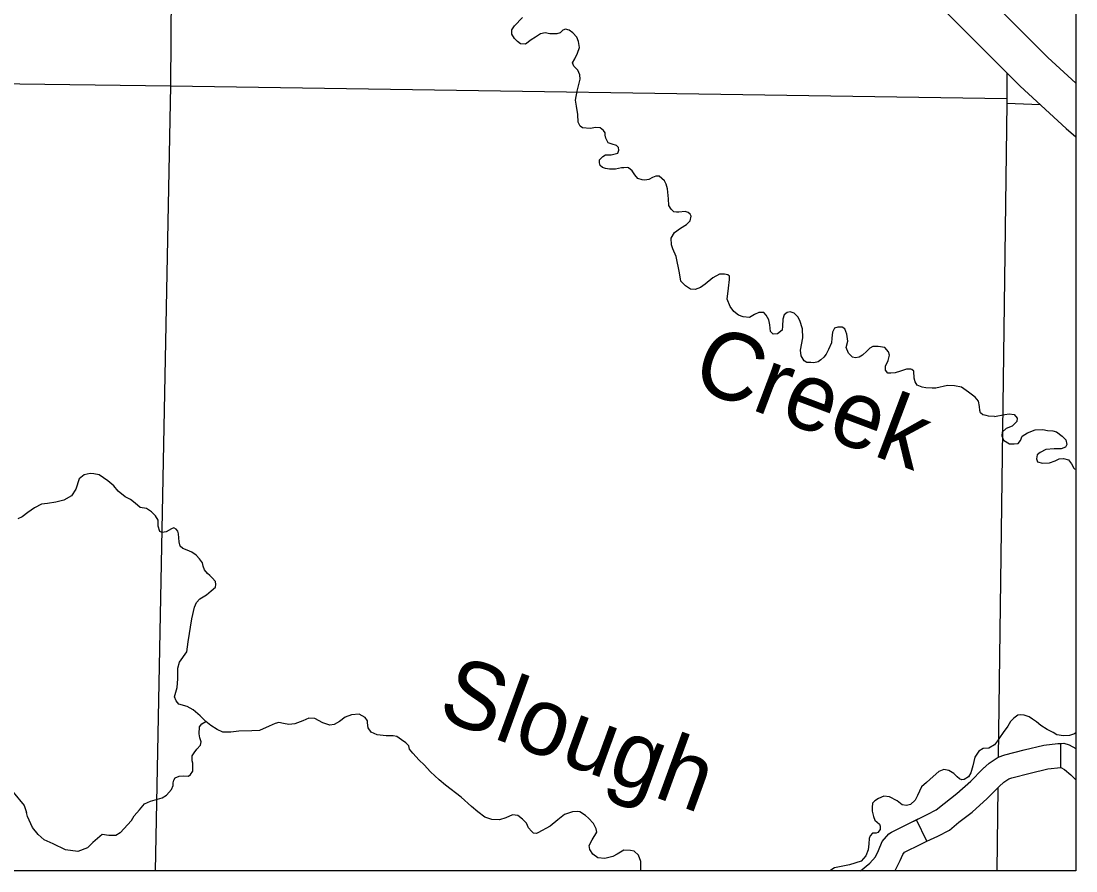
# Model space of a CAD drawing. Extents: x 8749 to 11879, y 13275 to 15339.
# Drawn here: x 10827.5 to 10959.7, y 13439.9 to 13546.4 of the extents above; entities that cross this region are included whole.
import ezdxf

# ---------------------------------------------------------------- set-up
doc = ezdxf.new("R2010")
doc.units = 0
for name, color, linetype in [('Level 10', 7, 'Continuous'), ('Level 35', 7, 'Continuous'), ('Level 4', 7, 'Continuous'), ('Level 45', 7, 'Continuous'), ('Level 5', 7, 'Continuous'), ('R_Draft', 7, 'Continuous')]:
    doc.layers.add(name, color=color, linetype=linetype)

msp = doc.modelspace()

# ---------------------------------------------------------------- linework, layer by layer
at = {"layer": 'Level 10'}
for points in [[(10959.72, 13538.61), (10956.22, 13541.83), (10954.17, 13543.9), (10948.32, 13549.78), (10940.49, 13557.65), (10939.11, 13559.13), (10938.56, 13559.8), (10938.03, 13560.67), (10937.75, 13561.23), (10937.61, 13561.73), (10937.29, 13563.06), (10937.16, 13563.75), (10937.14, 13565.49), (10937.14, 13568.12), (10937.11, 13569.39), (10936.92, 13570.54), (10936.72, 13571.84), (10936.36, 13573.13), (10935.94, 13574.18), (10935.26, 13575.82), (10934.06, 13578.06)], [(10929.65, 13575.7), (10930.73, 13573.68), (10931.3, 13572.3), (10931.61, 13571.52), (10931.83, 13570.77), (10931.99, 13569.76), (10932.12, 13568.93), (10932.14, 13568.06), (10932.14, 13565.46), (10932.17, 13563.25), (10932.4, 13562.01), (10932.76, 13560.51), (10933.05, 13559.45), (10933.65, 13558.23), (10934.48, 13556.89), (10935.34, 13555.84), (10936.89, 13554.18), (10944.77, 13546.25), (10950.62, 13540.37), (10952.75, 13538.23), (10958.49, 13532.93), (10959.72, 13531.89)]]:
    msp.add_lwpolyline(points, dxfattribs=at)
at = {"layer": 'Level 35'}
for points in [[(10889.33, 13545.83), (10890.36, 13546.87)], [(10898.82, 13532.94), (10897.89, 13533.01), (10897.59, 13533.24), (10897.31, 13533.75), (10897.28, 13534.68), (10897.13, 13535.74), (10897.01, 13536.48), (10897.21, 13537.64), (10897.59, 13539.11), (10897.54, 13539.69), (10897.28, 13540.25), (10896.8, 13540.75), (10896.63, 13541.16), (10896.93, 13541.66), (10897.23, 13542.39), (10897.49, 13543.08), (10897.36, 13543.84), (10897.18, 13544.39), (10896.65, 13544.92), (10896.2, 13545.28), (10895.74, 13545.38), (10895.41, 13545.25), (10895.06, 13544.92), (10894.66, 13544.8), (10893.77, 13544.82), (10893.17, 13544.92), (10892.61, 13544.8), (10891.98, 13544.39), (10891.42, 13544.04), (10890.72, 13543.53), (10890.11, 13543.56), (10889.71, 13543.84), (10889.33, 13544.21), (10889, 13544.75), (10889, 13545.3), (10889.33, 13545.83)], [(10904.08, 13527.62), (10903.65, 13528.01), (10903.49, 13528.04), (10903.04, 13528.01), (10902.74, 13527.99), (10902, 13527.86), (10901.27, 13527.86), (10900.77, 13527.91), (10900.39, 13528.04), (10900.08, 13528.32), (10900.01, 13528.62), (10900.01, 13529.02), (10900.41, 13529.45), (10900.77, 13529.63), (10901.47, 13529.63), (10902.28, 13529.86), (10902.43, 13530.24), (10902.38, 13530.57), (10902.13, 13530.82), (10901.6, 13530.97), (10901.09, 13531.15), (10900.79, 13531.73), (10900.72, 13532.11), (10900.72, 13532.41), (10900.49, 13532.69), (10900.08, 13533.02), (10899.53, 13533.07), (10898.82, 13532.94)], [(10910.79, 13513.23), (10910.21, 13513.82), (10910.01, 13514.83), (10909.61, 13516.9), (10909.18, 13517.84), (10909.03, 13518.37), (10909, 13519.18), (10909.4, 13519.91), (10910.16, 13520.44), (10910.89, 13520.9), (10911.35, 13521.38), (10911.48, 13521.96), (10911.37, 13522.21), (10911.12, 13522.42), (10910.74, 13522.52), (10909.96, 13522.44), (10909.66, 13522.44), (10909.3, 13522.49), (10909, 13522.82), (10908.7, 13523.28), (10908.65, 13524.11), (10908.52, 13525.37), (10908.37, 13525.98), (10908.17, 13526.39), (10907.46, 13526.97), (10907.06, 13526.97), (10906.63, 13526.79), (10906.17, 13526.56), (10905.69, 13526.46), (10905.36, 13526.49), (10904.81, 13526.69), (10904.43, 13527.14), (10904.08, 13527.62)], [(10926.87, 13503.57), (10926.5, 13503.62), (10925.99, 13503.62), (10925.64, 13503.8), (10925.29, 13504.46), (10925.19, 13505.14), (10925.49, 13506.71), (10925.44, 13507.82), (10925.11, 13508.88), (10924.88, 13509.31), (10924.4, 13509.77), (10923.9, 13509.94), (10923.52, 13509.89), (10923.17, 13509.59), (10922.99, 13509.03), (10922.96, 13508.17), (10922.89, 13507.64), (10922.33, 13507.21), (10921.75, 13507.16), (10921.42, 13507.49), (10921.35, 13508.33), (10921.22, 13508.96), (10920.89, 13509.56), (10920.59, 13509.87), (10919.98, 13509.89), (10919.45, 13509.62), (10918.8, 13509.24), (10917.99, 13509.31), (10917.43, 13509.56), (10916.85, 13509.99), (10916.37, 13510.63), (10916.02, 13511.54), (10916.19, 13512.93), (10916.3, 13513.99), (10916.3, 13514.42), (10916.09, 13514.6), (10915.66, 13514.67), (10915.06, 13514.67), (10914.2, 13514.22), (10913.26, 13513.41), (10912.66, 13513), (10912, 13512.75), (10911.4, 13512.8), (10910.79, 13513.23)], [(10939.42, 13502.52), (10939.17, 13502.74), (10939.02, 13502.79), (10938.49, 13502.79), (10937.73, 13502.51), (10937.08, 13502.33), (10936.5, 13502.26), (10936.14, 13502.28), (10935.87, 13502.64), (10935.87, 13503.14), (10936.17, 13503.85), (10936.35, 13504.53), (10936.22, 13504.96), (10935.76, 13505.47), (10934.93, 13505.62), (10934.27, 13505.6), (10933.87, 13505.39), (10933.52, 13505.01), (10932.96, 13504.51), (10932.53, 13504.28), (10932.08, 13504.21), (10931.72, 13504.28), (10931.22, 13504.76), (10930.94, 13505.49), (10931.12, 13506.28), (10931.02, 13507.14), (10930.76, 13507.82), (10930.41, 13508.05), (10929.88, 13508.05), (10929.45, 13507.9), (10929.2, 13507.39), (10929.12, 13506.66), (10929.07, 13506.05), (10928.69, 13505.24), (10928.41, 13504.63), (10928.11, 13504.28), (10927.76, 13503.93), (10927.4, 13503.67), (10926.87, 13503.57)], [(10949.5, 13496.85), (10948.77, 13496.86), (10948.46, 13496.96), (10948.06, 13497.06), (10947.78, 13497.29), (10947.68, 13497.59), (10947.63, 13498.1), (10947.5, 13498.76), (10947.1, 13499.26), (10946.24, 13499.87), (10945.36, 13500.5), (10944.5, 13500.68), (10943.64, 13500.73), (10942.18, 13500.4), (10941.7, 13500.37), (10940.91, 13500.43), (10940.46, 13500.5), (10939.83, 13500.75), (10939.55, 13501.18), (10939.45, 13501.66), (10939.42, 13502.52)], [(10949.5, 13496.85), (10950.83, 13497.1), (10951.36, 13497.17), (10951.97, 13497.1), (10952.35, 13496.62), (10952.3, 13496.19), (10951.74, 13495.63), (10950.96, 13495.35), (10950.46, 13494.85), (10950.43, 13494.42), (10950.66, 13493.86), (10951.39, 13493.41), (10951.97, 13493.41), (10952.48, 13493.43), (10952.78, 13493.84), (10952.98, 13494.37), (10953.64, 13494.8), (10954.6, 13495.15), (10955.56, 13495.2), (10956.16, 13495.08), (10956.82, 13495.02), (10957.3, 13494.9), (10957.98, 13494.39), (10958.46, 13493.91), (10958.59, 13493.33), (10958.41, 13493), (10957.86, 13492.77), (10957, 13492.77), (10955.96, 13492.7), (10955.25, 13492.32), (10954.88, 13492.04), (10954.77, 13491.51), (10954.9, 13491.16), (10955.53, 13490.98), (10956.39, 13491.03), (10957.12, 13491.28), (10957.6, 13491.51), (10958.18, 13491.56), (10958.77, 13491.41), (10959.17, 13490.9), (10959.47, 13490.37), (10959.59, 13490.22)], [(10839.13, 13488.15), (10838.38, 13488.75), (10837.82, 13489.13), (10837.27, 13489.54), (10836.61, 13489.64), (10836.15, 13489.69), (10835.42, 13489.51), (10834.79, 13489), (10834.35, 13487.74), (10833.8, 13486.88), (10832.86, 13486.34), (10831.85, 13486.09), (10830.81, 13485.94), (10830.05, 13485.84), (10829.19, 13485.38), (10828.33, 13484.8), (10827.62, 13484.24), (10827.09, 13483.99)], [(10959.72, 13490.17), (10959.59, 13490.22)], [(10851.86, 13476.16), (10851.46, 13476.6), (10851.15, 13476.9), (10850.85, 13477.16), (10850.49, 13477.61), (10850.34, 13478.09), (10850.24, 13478.5), (10849.86, 13479.01), (10849.46, 13479.44), (10848.92, 13479.82), (10848.32, 13480.07), (10847.76, 13480.27), (10847.43, 13480.58), (10847.3, 13481.13), (10847.25, 13482.12), (10847.15, 13482.45), (10846.95, 13482.71), (10846.65, 13482.88), (10846.34, 13482.76), (10845.68, 13482.38), (10845.2, 13482.28), (10844.87, 13482.43), (10844.67, 13483.09), (10844.7, 13483.82), (10844.34, 13484.38), (10843.86, 13484.88), (10843.2, 13485.29), (10842.42, 13485.42), (10841.81, 13485.95), (10841.23, 13486.43), (10840.55, 13486.78), (10839.66, 13487.49), (10839.13, 13488.15)], [(10847.13, 13465.28), (10847.35, 13466.02), (10848.29, 13467.34), (10848.44, 13468.58), (10848.9, 13471.47), (10849.23, 13472.94), (10849.48, 13473.5), (10849.91, 13473.98), (10850.72, 13474.48), (10851.33, 13474.99), (10851.86, 13475.45), (10851.91, 13475.78), (10851.86, 13476.16)], [(10854.79, 13457.4), (10853.78, 13457.25), (10852.77, 13457.25), (10852.09, 13457.58), (10851.28, 13458.08), (10850.67, 13458.61), (10849.94, 13459.3), (10849.08, 13460.06), (10848.32, 13460.46), (10847.28, 13460.79), (10846.95, 13461.17), (10846.72, 13461.71), (10847.08, 13462.87), (10847.13, 13463.94), (10847.15, 13464.54), (10847.13, 13465.28)], [(10805.9, 13464.5), (10806.56, 13463.42), (10806.21, 13462.26), (10806.36, 13461.3), (10807.16, 13459.28), (10808.73, 13457.97), (10810.69, 13456.3), (10813.46, 13454.49), (10815.88, 13453.43), (10818.15, 13453.12), (10821.48, 13451.91), (10824.35, 13451.41), (10826.52, 13449.74), (10827.88, 13448.08), (10828.17, 13447.18)], [(10872.12, 13456.93), (10871.39, 13457.27), (10871.01, 13457.8), (10870.91, 13458.41), (10870.91, 13458.67), (10870.61, 13459.1), (10869.87, 13459.5), (10868.91, 13459.45), (10868.1, 13459.12), (10867.42, 13458.61), (10866.76, 13458.21), (10866.2, 13458.13), (10865.32, 13458.41), (10864.31, 13458.97), (10863.55, 13459.02), (10862.81, 13458.67), (10861.83, 13458.29), (10861.04, 13458.21), (10860.38, 13458.34), (10859.8, 13458.46), (10859.35, 13458.36), (10858.61, 13458.03), (10857.37, 13457.47), (10856.41, 13457.42), (10854.79, 13457.4)], [(10952.45, 13459.4), (10951.93, 13459.02), (10951.5, 13458.59), (10951.17, 13458.03), (10950.61, 13457.22), (10950.16, 13456.54), (10949.88, 13456.19), (10949.5, 13455.68), (10948.81, 13455.27), (10948.11, 13455.2), (10947.57, 13454.87), (10947.07, 13454.13), (10946.81, 13453.04), (10946.56, 13452.16), (10946.26, 13451.68), (10945.73, 13451.32)], [(10959.72, 13457.17), (10959.54, 13457.05), (10958.91, 13456.84), (10958.15, 13456.79), (10957.34, 13456.92), (10956.86, 13457.2), (10956.12, 13457.58), (10955.31, 13458.11), (10954.78, 13458.54), (10954.28, 13458.9), (10953.85, 13459.17), (10953.24, 13459.38), (10952.81, 13459.43), (10952.45, 13459.4)], [(10839.9, 13444.63), (10841.34, 13446.18), (10841.67, 13446.76), (10842.33, 13447.52), (10842.96, 13448.26), (10843.72, 13448.61), (10845.19, 13449.04), (10845.72, 13449.37), (10846.35, 13450.06), (10846.55, 13450.59), (10846.58, 13450.89), (10846.63, 13451.25), (10846.81, 13451.53), (10847.31, 13451.75), (10847.84, 13451.8), (10848.5, 13451.75), (10848.73, 13451.96), (10849.03, 13452.36), (10849.01, 13452.79), (10849.03, 13453.38), (10848.96, 13453.68), (10848.93, 13454.29), (10849.21, 13454.67), (10849.52, 13455.12), (10850, 13455.63), (10850.07, 13456.06), (10849.92, 13456.54), (10849.84, 13457.07), (10849.87, 13457.91), (10850.17, 13458.32), (10850.67, 13458.61)], [(10880.69, 13450.61), (10879.92, 13451.28), (10878.8, 13452.29), (10878.02, 13453.18), (10877.41, 13453.76), (10876.6, 13454.62), (10876.2, 13455.13), (10876.1, 13455.53), (10875.74, 13455.94), (10875.19, 13456.29), (10874.58, 13456.7), (10874.15, 13456.8), (10873.24, 13456.8), (10872.12, 13456.93)], [(10945.73, 13451.32), (10945.4, 13451.28), (10945.12, 13451.41), (10944.82, 13451.66), (10944.42, 13452.09), (10943.81, 13452.47), (10943.17, 13452.57), (10942.54, 13452.32), (10941.81, 13451.71), (10941, 13450.93), (10940.37, 13450.39), (10939.86, 13449.3), (10939.56, 13448.75), (10939, 13448.21), (10938.47, 13448.06), (10937.94, 13448.14), (10937.3, 13448.67), (10936.37, 13449.15), (10935.66, 13449.25), (10934.97, 13448.95), (10934.52, 13448.65), (10934.24, 13448.37), (10934.16, 13447.83), (10934.16, 13447.35), (10934.34, 13446.67), (10934.52, 13446.24), (10935.08, 13445.71), (10935.18, 13445.48), (10935.2, 13445.07)], [(10892.26, 13444.63), (10892.09, 13444.55), (10891.73, 13444.6), (10891.46, 13444.85), (10891.1, 13445.26), (10890.85, 13445.84), (10890.37, 13446.37), (10889.78, 13446.83), (10889.1, 13446.88), (10888.24, 13446.5), (10887.46, 13446.25), (10886.52, 13446.3), (10885.61, 13446.6), (10884.75, 13447.29), (10883.96, 13447.92), (10882.67, 13449.11), (10880.69, 13450.61)], [(10839.9, 13444.63), (10839.36, 13444.3), (10838.5, 13444.3), (10837.65, 13444.45), (10836.49, 13443.44), (10835.83, 13442.74), (10834.62, 13442.28), (10833.06, 13442.49), (10831.5, 13443.24), (10830.39, 13443.75), (10829.63, 13444.45), (10828.93, 13445.31), (10828.32, 13446.67), (10828.17, 13447.18)], [(10905.17, 13439.87), (10905.19, 13440.05), (10905.19, 13441.04), (10904.89, 13441.82), (10904.36, 13442.33), (10903.88, 13442.43), (10903.04, 13442.45), (10902.21, 13441.97), (10901.68, 13441.67), (10900.66, 13441.44), (10899.78, 13441.52), (10899.17, 13441.97), (10898.77, 13442.53), (10898.71, 13443.06), (10899.09, 13443.77), (10899.65, 13444.71), (10899.6, 13445.16), (10899.25, 13445.8), (10898.64, 13446.46), (10898.23, 13446.81), (10897.55, 13447.27), (10897.2, 13447.32), (10896.61, 13447.29), (10895.6, 13446.94), (10894.79, 13446.28), (10893.83, 13445.49), (10892.26, 13444.63)], [(10935.2, 13445.07), (10934.87, 13444.68), (10934.7, 13444.58), (10934.24, 13444.58), (10933.94, 13444.27), (10933.81, 13443.92), (10933.76, 13443.26), (10933.68, 13442.52), (10933.4, 13441.74), (10932.8, 13441.08), (10931.35, 13440.62), (10929.46, 13440.24), (10928.89, 13439.87)]]:
    msp.add_lwpolyline(points, dxfattribs=at)
at = {"layer": 'Level 4'}
for points in [[(10951.07, 13539.92), (10951.05, 13536.7), (10951.05, 13536.12), (10949.97, 13454.11)], [(10949.92, 13450.29), (10949.79, 13439.87)]]:
    msp.add_lwpolyline(points, dxfattribs=at)
at = {"layer": 'Level 45'}
for p, q in [((10957.81, 13452.84), (10957.81, 13455.84)), ((10941.03, 13443.58), (10939.73, 13446.28))]:
    msp.add_line(p, q, dxfattribs=at)
for points in [[(10932.73, 13439.87), (10933.89, 13440.85), (10934.58, 13441.63), (10934.98, 13442.43), (10935.44, 13443.54), (10936.29, 13444.52), (10936.59, 13444.73), (10938.94, 13445.9), (10941.08, 13446.93), (10942.21, 13447.51), (10943.19, 13448.33), (10944.79, 13449.55), (10946.54, 13451.13), (10948.03, 13452.62), (10948.85, 13453.37), (10949.96, 13454.11), (10950.8, 13454.4), (10953.24, 13455.04), (10955.71, 13455.62), (10957.46, 13455.82), (10958.19, 13455.86), (10958.86, 13455.69), (10959.72, 13455.21)], [(10948.06, 13452.65), (10948.85, 13453.37), (10949.96, 13454.11), (10950.8, 13454.4), (10953.24, 13455.04), (10955.71, 13455.62), (10957.46, 13455.82), (10957.91, 13455.85)], [(10957.91, 13455.85), (10958.19, 13455.86), (10958.86, 13455.69), (10959.72, 13455.21)], [(10939.73, 13446.28), (10941.08, 13446.93), (10942.21, 13447.51), (10943.19, 13448.33), (10944.79, 13449.55), (10946.54, 13451.13), (10948.03, 13452.62), (10948.06, 13452.65)], [(10950.09, 13450.44), (10950.7, 13451), (10951.3, 13451.4), (10951.67, 13451.52), (10953.97, 13452.13), (10956.22, 13452.66), (10957.81, 13452.84)], [(10957.81, 13452.84), (10958.28, 13452.58), (10959.1, 13451.93), (10959.72, 13451.28), (10959.72, 13451.28)], [(10941.03, 13443.58), (10942.41, 13444.24), (10943.88, 13444.99), (10945.06, 13445.99), (10946.7, 13447.24), (10948.61, 13448.95), (10950.11, 13450.45), (10950.09, 13450.44)], [(10932.73, 13439.87), (10933.89, 13440.85), (10934.58, 13441.63), (10934.98, 13442.43), (10935.44, 13443.54), (10936.29, 13444.52), (10936.59, 13444.73), (10938.94, 13445.9), (10939.73, 13446.28)], [(10937.02, 13439.87), (10937.08, 13439.93), (10937.7, 13441.18), (10938.02, 13441.94), (10938.25, 13442.2), (10940.26, 13443.21), (10941.03, 13443.58)]]:
    msp.add_lwpolyline(points, dxfattribs=at)
at = {"layer": 'Level 5'}
for points in [[(10846.99, 13644.47), (10846.23, 13538.28)], [(10776.87, 13539.22), (10846.23, 13538.28)], [(10846.23, 13538.28), (10844.32, 13439.87)], [(10846.23, 13538.28), (10951.05, 13536.7)], [(10951.05, 13536.12), (10955.24, 13535.94)]]:
    msp.add_lwpolyline(points, dxfattribs=at)
at = {"layer": 'R_Draft'}
msp.add_lwpolyline([(9678.09, 14456.3), (10959.72, 14456.3), (10959.72, 13439.87), (9678.09, 13439.87)], close=True, dxfattribs=at)

# ---------------------------------------------------------------- texts
at = {"layer": 'Level 35'}
for s, rotation, p in [('Creek', 339.3298, (10911.23, 13500.65)), ('Slough', 339.964, (10879.45, 13459.13))]:
    msp.add_text(s, height=8.448, rotation=rotation, dxfattribs=at).set_placement(p)

doc.saveas('drawing.dxf')
